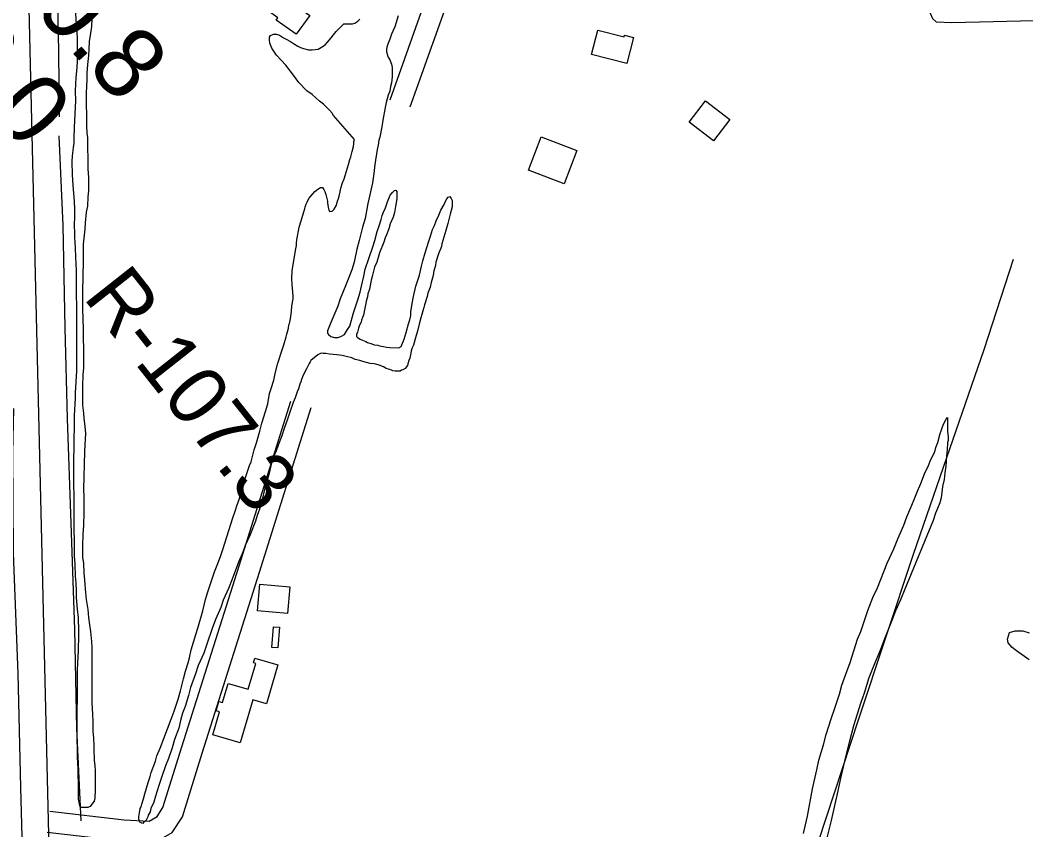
# Model space of a CAD drawing. Extents: x 3625074 to 3663148, y 511451 to 537151.
# Drawn here: x 3646582 to 3648000, y 519376 to 520518 of the extents above; entities that cross this region are included whole.
import ezdxf

# ---------------------------------------------------------------- set-up
doc = ezdxf.new("R2010")
doc.units = 0
for name, color, linetype in [('V-BLDG-OTLN', 7, 'Continuous'), ('V-RIVR-RANG-IDEN', 7, 'Continuous'), ('V-ROAD-CNTR', 7, 'Continuous'), ('V-SITE-VEGE', 7, 'Continuous'), ('V-SURV-IDEN', 7, 'Continuous'), ('V-TOPO-SHOR', 7, 'Continuous')]:
    doc.layers.add(name, color=color, linetype=linetype)

msp = doc.modelspace()

# ---------------------------------------------------------------- linework, layer by layer
at = {"layer": 'V-BLDG-OTLN'}
for points in [[(3646924.3, 520570.9), (3646962.7, 520543.3), (3646964, 520545.1), (3646977.3, 520535.6), (3646976.4, 520534.4), (3646990.3, 520524.5), (3646971.2, 520498), (3646943.1, 520518.1), (3646945.5, 520521.4), (3646908.1, 520548.3)], [(3647437.4, 520456.8), (3647387.5, 520469.7), (3647396.3, 520504), (3647433.5, 520494.5), (3647434.1, 520496.6), (3647446.8, 520493.3)], [(3647548.2, 520404.1), (3647582.7, 520377.7), (3647559.6, 520347.6), (3647525.1, 520374)], [(3647349.1, 520287.3), (3647298.8, 520306.4), (3647316.6, 520353.3), (3647367, 520334.2)], [(3646916.8, 519684.7), (3646920, 519722.3), (3646962.3, 519718.7), (3646959.1, 519681.1)], [(3646947.4, 519661.6), (3646945.3, 519632.5), (3646936.9, 519633.1), (3646939, 519662.2)], [(3646909.9, 519559.4), (3646892.2, 519498.8), (3646853.7, 519510), (3646863.2, 519542.4), (3646858.4, 519543.8), (3646862.3, 519557), (3646867.2, 519555.5), (3646875.1, 519582.5), (3646903.5, 519574.2), (3646914.1, 519610.5), (3646910.9, 519611.4), (3646912.9, 519618.3), (3646945.4, 519608.8), (3646929.4, 519553.8)]]:
    msp.add_lwpolyline(points, close=True, dxfattribs=at)
at = {"layer": 'V-ROAD-CNTR'}
for points in [[(3647103.5, 520405.7), (3647165.8, 520580.9), (3647217, 520734.8), (3647242, 520835.3), (3647307.2, 521044), (3647372.9, 521261.5), (3647473.2, 521564.4), (3647555.2, 521830.6), (3647553.9, 521865.8)], [(3647131.7, 520395.6), (3647194.2, 520571.2), (3647245.9, 520726.5), (3647270.9, 520827.2), (3647335.9, 521035.2), (3647354.6, 521097.2)], [(3646651.3, 518144.1), (3646593.2, 520594.6)], [(3646620.1, 519372.6), (3646726.2, 519360.2), (3646771.1, 519357.8), (3646796.4, 519372.2), (3646810.7, 519394.5), (3646838.7, 519484), (3646919.5, 519739.5), (3646992.3, 519971.7)], [(3646623.6, 519402.4), (3646728.8, 519390.1), (3646763.9, 519388.2), (3646775.1, 519394.6), (3646783.3, 519407.3), (3646810.1, 519493), (3646890.9, 519748.5), (3646963.7, 519980.7)]]:
    msp.add_lwpolyline(points, dxfattribs=at)
at = {"layer": 'V-SITE-VEGE'}
for points in [[(3646659.1, 520235.8), (3646659.1, 520251.4), (3646658.6, 520262.2), (3646656.7, 520285.1), (3646655.7, 520299.8), (3646655.3, 520318.8), (3646655.8, 520326.6), (3646656.8, 520334), (3646657.3, 520338.8), (3646658.2, 520344.2), (3646658.2, 520351.5), (3646658.8, 520367.2), (3646660.3, 520404.3), (3646659.8, 520418.4), (3646660.8, 520437), (3646661.8, 520445.8), (3646662.8, 520458.9), (3646662.8, 520488.2), (3646662.4, 520504.8), (3646660.9, 520517.5), (3646660.4, 520529.3)], [(3647115, 520524.3), (3647110.1, 520508.7), (3647105.7, 520498.4), (3647103.2, 520491.1), (3647100.3, 520484.3), (3647098.8, 520479.9), (3647098.3, 520476.5), (3647098.3, 520473.5), (3647099.8, 520468.6), (3647100.3, 520466.2), (3647101.7, 520464.2), (3647103.2, 520461.8), (3647105.6, 520455.9), (3647106.6, 520451.1)], [(3646682.9, 520520), (3646682.4, 520509.2), (3646680.9, 520496.5), (3646679.4, 520488.2), (3646678.9, 520476.5), (3646678.4, 520468.2), (3646676.9, 520455.5), (3646675.9, 520443.3), (3646675.9, 520434), (3646674.9, 520415.5), (3646674.9, 520397.4), (3646675.4, 520385.7), (3646675.4, 520365.2), (3646675.8, 520361.8), (3646675.8, 520358.8), (3646676.8, 520352.5), (3646676.8, 520334.9), (3646677.3, 520325.6), (3646677.2, 520308.1), (3646678.2, 520295.9), (3646678.2, 520277.3), (3646677.2, 520269), (3646676.7, 520255.8), (3646675.2, 520247), (3646673.7, 520231.9), (3646673.2, 520223.1), (3646670.7, 520202.1), (3646670.7, 520174.8)], [(3647002.1, 520477.1), (3647007, 520480), (3647011.9, 520483.4), (3647015.3, 520486.8), (3647020.7, 520493.2), (3647023.6, 520497.1), (3647027.6, 520501.9), (3647038.3, 520512.7), (3647050.5, 520512.6), (3647053.9, 520513.6), (3647058.3, 520516.5), (3647060.8, 520519.5)], [(3646912.1, 519911.8), (3646915, 519922), (3646919.9, 519938.1), (3646922.9, 519949.4), (3646927.8, 519966), (3646931.2, 519976.7), (3646933.6, 519991.3), (3646936.1, 519998.2), (3646939.5, 520010.4), (3646941.5, 520019.6), (3646945.4, 520034.3), (3646951.3, 520052.8), (3646953.8, 520060.2), (3646957.2, 520071.4), (3646958.2, 520075.3), (3646958.7, 520078.2), (3646960.1, 520083.6), (3646960.6, 520088), (3646961.6, 520089.9), (3646962.1, 520091.9), (3646963.1, 520096.8), (3646964.6, 520107), (3646965.1, 520114.8), (3646967, 520125.1), (3646967, 520128.5), (3646965.6, 520145.1), (3646965.1, 520153.4), (3646965.6, 520164.6), (3646970, 520192.9), (3646971.5, 520200.3), (3646971.5, 520203.2), (3646972, 520208.1), (3646975.5, 520226.1), (3646978.4, 520234.9), (3646981.8, 520247.6), (3646983.3, 520252), (3646983.8, 520254.9), (3646985.3, 520258.3), (3646986.7, 520261.3), (3646989.2, 520266.6), (3646997.5, 520276.4), (3647001.9, 520279.8), (3647005.3, 520281.8), (3647008.2, 520281.8), (3647010.2, 520279.3), (3647011.6, 520276.4), (3647013.1, 520272), (3647015.5, 520262.7), (3647015.5, 520259.8), (3647016.5, 520252), (3647017, 520250), (3647018.4, 520248.1), (3647021.9, 520248.5), (3647024.8, 520251.5), (3647028.2, 520256.8), (3647028.7, 520259.3), (3647029.2, 520262.7), (3647030.7, 520266.6), (3647031.7, 520269.5), (3647033.1, 520275.9), (3647034.1, 520281.2), (3647036.6, 520288.6), (3647039, 520294.4), (3647042, 520305.1), (3647044.9, 520314.4), (3647046.9, 520321.3), (3647048.3, 520325.2), (3647050.3, 520332.5), (3647051.8, 520339.8), (3647052.3, 520344.2), (3647052.3, 520346.6), (3647053.2, 520349.6), (3647024, 520383.3), (3647022, 520386.7), (3647018.1, 520391.1), (3647009.9, 520399.4), (3647004, 520403.8), (3646993.8, 520413.1), (3646986.4, 520418.5), (3646974.7, 520430.2), (3646967.4, 520440.5), (3646956.7, 520454.7), (3646943.5, 520468.8), (3646936.7, 520478.6), (3646933.8, 520485.5), (3646933.3, 520490.3), (3646933.3, 520493.8), (3646934.8, 520496.2), (3646939.2, 520498.1), (3646943.6, 520498.1), (3646947.5, 520496.7), (3646953.3, 520493.2), (3646957.2, 520491.3), (3646963.1, 520487.9), (3646967.5, 520484.9), (3646973.3, 520481.5), (3646977.2, 520479.5), (3646981.6, 520478.1), (3646988.5, 520476.1), (3646993.8, 520476.1), (3647002.1, 520477.1)], [(3647106.6, 520451.1), (3647106.6, 520437.9), (3647105.6, 520429.6), (3647104.1, 520424.2), (3647103.1, 520417.9), (3647100.7, 520412), (3647098.2, 520401.8), (3647096.8, 520394.9), (3647093.3, 520376.9), (3647091.8, 520367.6), (3647088.9, 520352.9), (3647087.9, 520348.5), (3647086.9, 520341.7), (3647085.4, 520335.4), (3647082, 520314.4), (3647080.5, 520301.7), (3647078.6, 520288.5), (3647075.1, 520271.4), (3647072.2, 520259.2), (3647068.2, 520238.2), (3647064.8, 520226), (3647059.9, 520207), (3647056.9, 520194.8), (3647053, 520176.7), (3647049.6, 520166), (3647043.7, 520150.4), (3647039.8, 520141.1), (3647033.4, 520125), (3647030, 520114.7), (3647021.2, 520094.7), (3647018.2, 520086.9), (3647015.3, 520079.6), (3647015.3, 520076.7), (3647016.8, 520074.7), (3647020.2, 520071.8), (3647025.1, 520070.3), (3647029.9, 520070.3), (3647034.3, 520071.8), (3647039.2, 520074.7), (3647043.6, 520081.5), (3647046.6, 520086.4), (3647051.9, 520105), (3647055.4, 520115.2), (3647057.8, 520122), (3647061.3, 520134.2), (3647063.2, 520143), (3647066.7, 520156.7), (3647068.6, 520166.9), (3647073.5, 520181.6), (3647079.4, 520198.2), (3647081.9, 520207), (3647085.3, 520220.1), (3647088.2, 520227.9), (3647091.2, 520236.7), (3647092.2, 520242.6), (3647094.6, 520248.4), (3647096.6, 520251.9), (3647098.5, 520257.7), (3647100, 520261.6), (3647103.9, 520270.9), (3647106.9, 520274.8), (3647109.8, 520277.7), (3647111.7, 520278.2), (3647113.2, 520276.2), (3647113.2, 520266.5), (3647112.2, 520260.1), (3647111.2, 520255.3), (3647109.7, 520246.5), (3647107.8, 520240.1), (3647103.9, 520230.9), (3647101.9, 520223.5), (3647098.5, 520215.2), (3647096.5, 520210.8), (3647094.6, 520205), (3647088.7, 520189.9), (3647084.8, 520176.7), (3647081.8, 520169.4), (3647078.4, 520156.2), (3647076.9, 520151.3), (3647074.5, 520138.6), (3647072, 520131.8), (3647071.5, 520127.9), (3647070, 520121.5), (3647069.5, 520118.1), (3647068.1, 520111.8), (3647066.1, 520102), (3647064.6, 520098.6), (3647063.2, 520094.7), (3647062.7, 520091.8), (3647060.2, 520087.9), (3647059.2, 520083.5), (3647057.8, 520078.1), (3647056.3, 520074.7), (3647056.3, 520071.7), (3647057.8, 520070.3), (3647061.2, 520067.8), (3647064.6, 520066.4), (3647069.5, 520064.9), (3647071.9, 520063.4), (3647077.8, 520061.5), (3647081.2, 520060)], [(3647081.2, 520060), (3647086.1, 520059.5), (3647088.5, 520058.5), (3647094.4, 520057.5), (3647098.3, 520056.6), (3647103.2, 520056.1), (3647115.8, 520056), (3647119.3, 520057.5), (3647120.2, 520059.9), (3647123.2, 520068.2), (3647126.1, 520077.5), (3647129.6, 520089.7), (3647131.5, 520095.1), (3647133, 520101.4), (3647133, 520106.8), (3647134.5, 520118.5), (3647136.4, 520128.3), (3647139.9, 520142.9), (3647142.8, 520151.2), (3647144.8, 520158.5), (3647147.7, 520171.2), (3647149.7, 520178.6), (3647153.1, 520189.8), (3647158, 520206.4), (3647160.5, 520213.2), (3647163.4, 520222.5), (3647166.4, 520228.3), (3647168.3, 520234.7), (3647172.2, 520243), (3647175.2, 520249.8), (3647179.6, 520258.1), (3647181.5, 520262.5), (3647183.5, 520265.9), (3647185.5, 520268.3), (3647187.9, 520269.3), (3647189.8, 520266.4), (3647191.3, 520263.5), (3647191.3, 520254.7), (3647189.8, 520249.3), (3647188.4, 520244.4), (3647186.4, 520236.6), (3647184.9, 520231.2), (3647182, 520221.5), (3647176.6, 520202.4), (3647176.1, 520198.5), (3647171.7, 520188.3), (3647168.2, 520176.6), (3647167.8, 520171.7), (3647165.3, 520164.4), (3647164.3, 520158), (3647161.4, 520147.8), (3647159.9, 520141.4), (3647157, 520133.1), (3647156, 520128.3), (3647152.1, 520116.5), (3647151.1, 520112.6), (3647149.6, 520108.2), (3647148.1, 520102.9), (3647146.7, 520098), (3647144.7, 520089.2), (3647142.7, 520081.4), (3647138.3, 520066.8), (3647136.4, 520059.4), (3647134.9, 520056), (3647133.4, 520051.6), (3647132.9, 520048.2), (3647131.5, 520041.4), (3647130, 520038), (3647128.5, 520033.1), (3647128, 520031.1), (3647124.6, 520026.7), (3647121.7, 520024.8), (3647119.7, 520024.3), (3647117.8, 520022.8), (3647110.9, 520022.8), (3647107.5, 520023.3), (3647104.6, 520024.8), (3647098.2, 520026.8), (3647094.3, 520029.2), (3647088, 520031.2), (3647083.6, 520032.6), (3647081.2, 520033.1), (3647075.3, 520033.6), (3647065, 520036.6), (3647061.1, 520038), (3647054.3, 520039.5), (3647049.4, 520041.5), (3647041.6, 520043.4), (3647036.2, 520044.9), (3647028.4, 520045.9), (3647018.2, 520046.9), (3647012.8, 520047.9), (3647009.4, 520047.9), (3647006.5, 520048.4), (3647001.6, 520045.9), (3646991.8, 520038.1), (3646990.8, 520036.2), (3646989.4, 520033.7), (3646985.9, 520026.4), (3646983, 520021.1), (3646980.1, 520014.7)], [(3646670.7, 520174.8), (3646670.2, 520160.1), (3646670.2, 520148.4), (3646669.7, 520144), (3646669.7, 520108.9), (3646670.1, 520098.1), (3646670.6, 520080.5), (3646670.6, 520069.8), (3646671.5, 520054.2), (3646671.5, 520027.3), (3646670.5, 520018), (3646670, 520001.4), (3646670, 519975.1), (3646671.4, 519963.8), (3646671.9, 519956.5), (3646673.3, 519944.8), (3646674.3, 519935), (3646673.3, 519918.9), (3646672.8, 519909.2), (3646671.3, 519856.4), (3646671.8, 519845.7), (3646671.7, 519823.7), (3646671.2, 519805.7), (3646670.2, 519792), (3646669.7, 519776.8), (3646669.7, 519760.2), (3646671.1, 519751.9), (3646671.6, 519738.3), (3646672.6, 519728), (3646674, 519710.4), (3646675, 519700.7), (3646677.4, 519686.5), (3646678.4, 519675.3), (3646679.8, 519665), (3646681.3, 519655.7), (3646682.7, 519641.6), (3646683.2, 519633.3), (3646683.1, 519555.2), (3646684.1, 519539), (3646684.5, 519528.8), (3646684.5, 519515.1), (3646685.5, 519505.4), (3646685.9, 519495.1), (3646685.9, 519486.3), (3646686.4, 519478), (3646686.4, 519473.6), (3646687.4, 519466.8), (3646687.9, 519459), (3646687.8, 519429.7), (3646687.3, 519423.3), (3646687.3, 519420.4), (3646686.3, 519416.5), (3646682.9, 519412.1), (3646680.5, 519408.7), (3646677.5, 519407.2), (3646667.8, 519407.2), (3646666.3, 519409.7), (3646665.3, 519415.1), (3646664.4, 519419), (3646664.4, 519441.9), (3646663.9, 519453.6), (3646663.9, 519461.9), (3646663, 519478.5), (3646663, 519488.8), (3646662.5, 519503.9), (3646662.6, 519600.6), (3646663.2, 519611.8), (3646664.1, 519627.9), (3646664.2, 519632.3), (3646664.7, 519647), (3646664.7, 519656.7), (3646664.2, 519674.8), (3646662.8, 519687), (3646661.3, 519703.6), (3646661.3, 519712.4), (3646660.9, 519724.1), (3646659.9, 519733.9), (3646659.4, 519750.5), (3646658.5, 519762.2), (3646658.5, 519785.6), (3646658, 519797.4), (3646658.1, 519846.7), (3646657.6, 519863.3), (3646657.7, 519898.9), (3646658.2, 519915), (3646658.2, 519925.8), (3646658.7, 519945.3), (3646658.7, 519960.4), (3646660.2, 519984.9), (3646660.2, 519992.2), (3646661.7, 520023.4), (3646661.8, 520115.2), (3646661.4, 520129.9), (3646661.4, 520165), (3646660.5, 520183.6), (3646660, 520196.8), (3646659, 520211.9), (3646659, 520217.3), (3646658.6, 520229), (3646658.6, 520233.9), (3646659.1, 520235.8)], [(3646980.1, 520014.7), (3646978.6, 520011.3), (3646977.6, 520007.9), (3646976.1, 520004.5), (3646974.2, 519998.1), (3646972.7, 519993.7), (3646969.8, 519985.4), (3646966.8, 519978.6), (3646962.9, 519966.4), (3646959.5, 519956.6), (3646954.1, 519942), (3646950.7, 519931.7), (3646945.8, 519918.6), (3646942.8, 519910.3), (3646938.4, 519900), (3646936.5, 519893.7), (3646932.5, 519877.1), (3646926.6, 519856.1), (3646923.2, 519841.9), (3646921.2, 519833.2), (3646916.3, 519819.5), (3646913.9, 519811.2), (3646905.6, 519791.2), (3646899.2, 519777), (3646895.8, 519767.8), (3646889.9, 519753.6), (3646881.1, 519729.7), (3646875.7, 519716.5), (3646868.3, 519699.9), (3646864.9, 519689.7), (3646857.6, 519672.6), (3646852.7, 519659.9), (3646845.8, 519639.4), (3646840.9, 519625.3), (3646833.1, 519607.7), (3646829.1, 519596), (3646822.3, 519576.5), (3646819.3, 519565.2), (3646814.4, 519550.1), (3646811, 519540.3), (3646808.1, 519530.1), (3646805.6, 519519.4), (3646799.7, 519503.3), (3646796.3, 519491.5), (3646790.9, 519476.4), (3646787, 519466.2), (3646781.1, 519449.6), (3646777.7, 519438.3), (3646772.8, 519423.2), (3646770.3, 519414.9), (3646766.4, 519406.1), (3646765.4, 519401.3), (3646762.5, 519396.4), (3646762, 519394.4), (3646759.1, 519388.6), (3646756.1, 519386.1), (3646754.7, 519384.7), (3646751.2, 519386.1), (3646750.3, 519388.1), (3646749.3, 519391), (3646749.3, 519394.4), (3646750.3, 519399.8), (3646751.3, 519406.2), (3646752.7, 519408.6), (3646753.7, 519412), (3646755.7, 519419.8), (3646757.6, 519426.7), (3646762.5, 519442.8), (3646765.5, 519451.1), (3646766.5, 519456.9), (3646772.8, 519473), (3646774.8, 519480.3), (3646779.2, 519491.1), (3646794.9, 519532.1), (3646799.3, 519543.3), (3646804.7, 519560.4), (3646808.1, 519572.1), (3646812.5, 519588.7), (3646815, 519599.9), (3646818.9, 519611.6), (3646820.9, 519618.5), (3646823.3, 519629.7), (3646829.7, 519651.6), (3646832.6, 519660.4), (3646839.5, 519684.8), (3646843.4, 519700.9), (3646846.4, 519711.7), (3646856.2, 519740), (3646859.6, 519749.3), (3646864.5, 519761.5), (3646867.9, 519771.2), (3646876.3, 519798.1), (3646881.7, 519816.1), (3646885.1, 519825.4), (3646887.5, 519832.7), (3646891, 519843.5), (3646893.4, 519853.2), (3646899.3, 519871.3), (3646905.2, 519889.8), (3646907.6, 519895.2), (3646912.1, 519911.8)], [(3647686.7, 519370.8), (3647692.1, 519395.2), (3647699, 519433.7), (3647705.4, 519460.6), (3647708.3, 519474.3), (3647714.7, 519495.7), (3647718.6, 519510.4), (3647725.5, 519532.3), (3647730.4, 519546), (3647737.3, 519567.5), (3647740.7, 519580.2), (3647747.6, 519599.2), (3647752.5, 519611.9), (3647762.7, 519645.1), (3647767.2, 519655.8), (3647777.4, 519685.1), (3647784.3, 519703.6), (3647790.7, 519717.3), (3647804.4, 519751.9), (3647813.7, 519772.4), (3647819.6, 519786.6), (3647827.9, 519805.6), (3647832.3, 519817.3), (3647839.2, 519833.9), (3647843.6, 519844.2), (3647847, 519853.5), (3647851.9, 519864.2), (3647857.3, 519878.3), (3647862.7, 519890), (3647866.1, 519898.3), (3647870.5, 519907.1), (3647872, 519911), (3647873, 519915.4), (3647875.9, 519922.3), (3647879.3, 519934.9), (3647880.8, 519938.9), (3647882.3, 519944.2), (3647884.2, 519949.1), (3647887.6, 519955.4), (3647889.6, 519957.4), (3647889.6, 519938.4), (3647890.5, 519930.1), (3647890.5, 519925.2), (3647889.6, 519921.8), (3647889.1, 519912.5), (3647888.1, 519903.2), (3647887.1, 519889), (3647885.6, 519879.3), (3647884.6, 519870), (3647882.6, 519860.2), (3647880.7, 519844.1), (3647878.7, 519837.3), (3647875.3, 519829), (3647872.8, 519822.7), (3647869.4, 519812.4), (3647829.2, 519715.3), (3647823.4, 519700.2), (3647816, 519685), (3647810.1, 519668.9), (3647800.8, 519645.5), (3647795, 519630.4), (3647785.2, 519607), (3647778.8, 519590.4), (3647771.9, 519568.9), (3647767.5, 519555.7), (3647757.2, 519522.5), (3647750.8, 519499.1), (3647746.4, 519480.6), (3647739.1, 519450.8), (3647735.1, 519430.8), (3647725.3, 519389.3), (3647717.9, 519359)], [(3648004.9, 519615.5), (3647986.8, 519628.2), (3647980.5, 519633.1), (3647975.1, 519639.9), (3647974.2, 519644.8), (3647977.1, 519654.1), (3647984.9, 519656.5), (3647995.7, 519656.5), (3648004.9, 519654)]]:
    msp.add_lwpolyline(points, dxfattribs=at)
at = {"layer": 'V-TOPO-SHOR'}
for points in [[(3647545.2, 520867), (3647640.8, 520774.7), (3647739.5, 520680.1), (3647824, 520589), (3647841.3, 520573.7), (3647852.7, 520562.2), (3647859.4, 520547.7), (3647862.9, 520535.8), (3647864.9, 520528), (3647868.4, 520520.1), (3647873.5, 520515.8), (3647895.5, 520514.5), (3648225.5, 520522.8), (3648385.7, 520530.4), (3648565.3, 520533.4), (3648796.4, 520540.9), (3648971.2, 520546.6)], [(3646618.1, 520775), (3646624.8, 520733.4), (3646630.4, 520684.4), (3646633.4, 520604.8), (3646636.1, 520474.4), (3646636.8, 520381.5)], [(3646636.5, 520354.7), (3646642.3, 520228.2), (3646645, 520084.2), (3646648.2, 519956.2), (3646653.5, 519808.6), (3646658.5, 519658.4), (3646661.4, 519518.7), (3646667.6, 519388.8)], [(3647982.1, 520180.3), (3647940.6, 520053), (3647888.2, 519900.7), (3647841.3, 519764.3), (3647763.8, 519532.2), (3647707.1, 519358.8), (3647664.4, 519235.3), (3647601.4, 519041), (3647523.2, 518786.6), (3647494.6, 518712.6), (3647489.6, 518698.6), (3647458.6, 518598.8), (3647391, 518398.6), (3647348.3, 518278.7), (3647316.7, 518167.4)], [(3646572.4, 519970), (3646571, 519907.9), (3646572.1, 519766.1), (3646578.9, 519596.4), (3646582.3, 519435.5), (3646586.1, 519296.8), (3646588.7, 519127.4), (3646591.2, 519030.6), (3646588, 518981.4), (3646583.8, 518952.2), (3646577.2, 518868.2), (3646571.1, 518809.1), (3646561.9, 518768.5), (3646515.2, 518624.9), (3646475.5, 518508)]]:
    msp.add_lwpolyline(points, dxfattribs=at)

# ---------------------------------------------------------------- texts
at = {"layer": 'V-RIVR-RANG-IDEN'}
msp.add_text('R-107.3', height=83, rotation=308.2968, dxfattribs=at).set_placement((3646669.5, 520127.2))
at = {"layer": 'V-SURV-IDEN'}
for s, rotation, p in [('411+70.8', 312.242, (3646346.1, 520812.6)), ('410+58.0', 311.2412, (3646216.2, 520754.1))]:
    msp.add_text(s, height=100, rotation=rotation, dxfattribs=at).set_placement(p)

doc.saveas('drawing.dxf')
